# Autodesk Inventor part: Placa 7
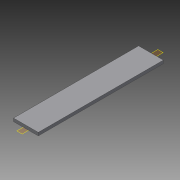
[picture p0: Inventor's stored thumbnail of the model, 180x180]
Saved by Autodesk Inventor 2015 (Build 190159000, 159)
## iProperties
Created: 2015-04
Part Number: Placa 7
Material: Generic
Document SubType Name: Modeling
Designer: suporte
Density: 1 g/cm^3
Appearance: Default
Author: suporte
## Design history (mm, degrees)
workplane "Work Plane1"
sketch "Sketch1"
  geometry: L1 (59.783, 506.099)-(-40.217, 506.099) reference; L2 (59.783, 0)-(-40.217, 0) reference; L3 (59.783, 506.099)-(-40.217, 506.099); L4 (-40.217, 506.099)-(-40.217, 0); L5 (-40.217, 0)-(59.783, 0); L6 (59.783, 0)-(59.783, 506.099); L7 (-40.217, 518.599)-(59.783, 518.599) reference; L8 (59.783, 506.099)-(59.783, 518.599); L9 (-40.217, 506.099)-(-40.217, 518.599); L10 (59.783, 506.099)-(-40.217, 506.099); L11 (-40.217, 506.099)-(-40.217, 0); L12 (-40.217, 0)-(59.783, 0); L13 (59.783, 0)-(59.783, 506.099); 1 further point
  constraints: 20 end point, 4 parallel, 2 horizontal, 2 perpendicular, 2 vertical
extrude "Extrusion1" new body sketch "Sketch1" distance "d0" = 12.5; taper "d1" = 0 deg
body "Solid1"
node "Reference1"
node "Reference2"
node "Reference3"
